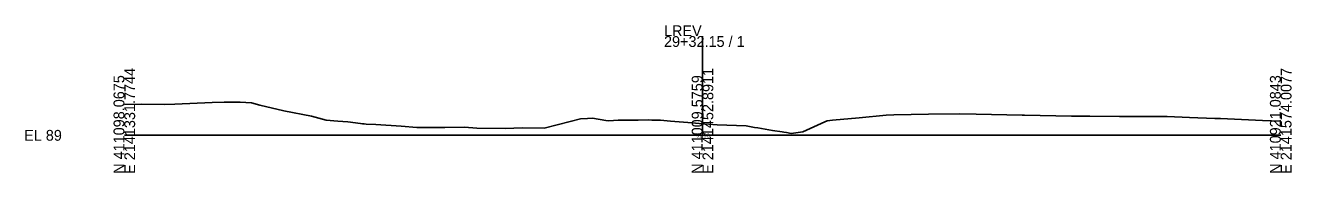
# Model space of a CAD drawing. Extents: x -14026 to 1303, y -10 to 9533.
# Drawn here: x 974.3 to 1302.8, y 7490.3 to 7528.5 of the extents above; entities that cross this region are included whole.
import ezdxf

# ---------------------------------------------------------------- set-up
doc = ezdxf.new("R2010")
doc.units = 0
for name, color, linetype in [('Default', 7, 'Continuous'), ('Exist Cross Section Cell', 7, 'Continuous'), ('Exist XS Center Line Elevation Label', 7, 'Continuous'), ('Exist XS Ground Line', 7, 'Continuous')]:
    doc.layers.add(name, color=color, linetype=linetype)

msp = doc.modelspace()

# ---------------------------------------------------------------- linework, layer by layer
at = {"layer": 'Exist Cross Section Cell'}
for p, q in [((1150, 7500), (1150, 7525.74)), ((1000, 7500), (1150, 7500)), ((1150, 7500), (1300, 7500))]:
    msp.add_line(p, q, dxfattribs=at)
at = {"layer": 'Exist XS Ground Line'}
msp.add_lwpolyline([(1000, 7507.96), (1004.4, 7508.05), (1010.41, 7508.02), (1013.12, 7508.09), (1022.79, 7508.52), (1025.87, 7508.58), (1030.08, 7508.58), (1033.02, 7508.39), (1035.18, 7507.8), (1041.39, 7506.37), (1048.58, 7504.97), (1052.37, 7503.92), (1055.4, 7503.7), (1058.01, 7503.54), (1061.26, 7503.04), (1061.82, 7502.98), (1062.23, 7502.97), (1062.77, 7502.93), (1065.28, 7502.77), (1071.78, 7502.34), (1075.89, 7502.03), (1083.17, 7502.01), (1088.23, 7502.11), (1091.43, 7501.83), (1098.8, 7501.78), (1103.28, 7501.93), (1108.9, 7501.83), (1115.63, 7503.58), (1118.3, 7504.27), (1120.13, 7504.39), (1121.41, 7504.44), (1124.87, 7503.88), (1125.73, 7503.72), (1128.09, 7503.91), (1133.26, 7503.96), (1135.96, 7504), (1136.88, 7503.97), (1138.4, 7503.93), (1139.1, 7503.92), (1141.66, 7503.7), (1147.28, 7503.21), (1150, 7502.98), (1150.49, 7502.94), (1153.8, 7502.74), (1161.28, 7502.44), (1163.51, 7502.04), (1164.33, 7501.92), (1168.17, 7501.29), (1170.64, 7500.89), (1171.06, 7500.82), (1171.79, 7500.7), (1173.03, 7500.5), (1176, 7500.93), (1181.69, 7503.47), (1182.34, 7503.75), (1183.74, 7503.9), (1190.62, 7504.58), (1197.63, 7505.26), (1199.6, 7505.31), (1208.58, 7505.52), (1216.55, 7505.54), (1220.97, 7505.48), (1232.95, 7505.21), (1233.51, 7505.2), (1245.74, 7504.97), (1250.46, 7504.93), (1258.13, 7504.86), (1267.41, 7504.9), (1269.2, 7504.91), (1270.51, 7504.89), (1276.36, 7504.65), (1282.9, 7504.39), (1283.52, 7504.37), (1284.36, 7504.33), (1295.29, 7503.87), (1300, 7503.71)], dxfattribs=at)

# ---------------------------------------------------------------- texts
at = {"layer": 'Default'}
msp.add_text('-', height=0.0001, dxfattribs=at).set_placement((1000, 7500))
at = {"layer": 'Exist Cross Section Cell'}
for s, p in [('LREV', (1140, 7525.74)), ('29+32.15 / 1', (1140, 7522.94)), ('EL 89', (974, 7498.6))]:
    msp.add_text(s, height=2.8, dxfattribs=at).set_placement(p)
for s, p in [('E 2141331.7744', (1002.8, 7490)), ('E 2141452.8911', (1152.8, 7490)), ('E 2141574.0077', (1302.8, 7490)), ('N 411098.0675', (1000, 7490)), ('N 411009.5759', (1150, 7490)), ('N 410921.0843', (1300, 7490))]:
    msp.add_text(s, height=2.8, rotation=90, dxfattribs=at).set_placement(p)
at = {"layer": 'Exist XS Center Line Elevation Label'}
msp.add_text('91.98', height=1, dxfattribs=at).set_placement((1148.38, 7499.48))

doc.saveas('drawing.dxf')
